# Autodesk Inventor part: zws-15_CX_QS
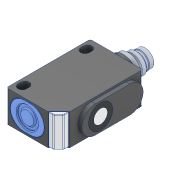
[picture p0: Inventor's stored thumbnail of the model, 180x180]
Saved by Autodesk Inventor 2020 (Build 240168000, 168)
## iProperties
Created: 2025-04
Part Number: zws-15_CX_QS
Material: Generisch
Description: STEP AP214
Document SubType Name: Modeling
Designer: Oliver Liedtke
Density: 1 g/cm^3
Appearance: Vorgabe
Title: zws-15_CX_QS.STEP
Revision Number: ANY
Sending System: SolidWorks 2024
Preprocessor: SwSTEP 2.0
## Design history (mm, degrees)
feature "Importiert1"
node "Volumenkörper1"
